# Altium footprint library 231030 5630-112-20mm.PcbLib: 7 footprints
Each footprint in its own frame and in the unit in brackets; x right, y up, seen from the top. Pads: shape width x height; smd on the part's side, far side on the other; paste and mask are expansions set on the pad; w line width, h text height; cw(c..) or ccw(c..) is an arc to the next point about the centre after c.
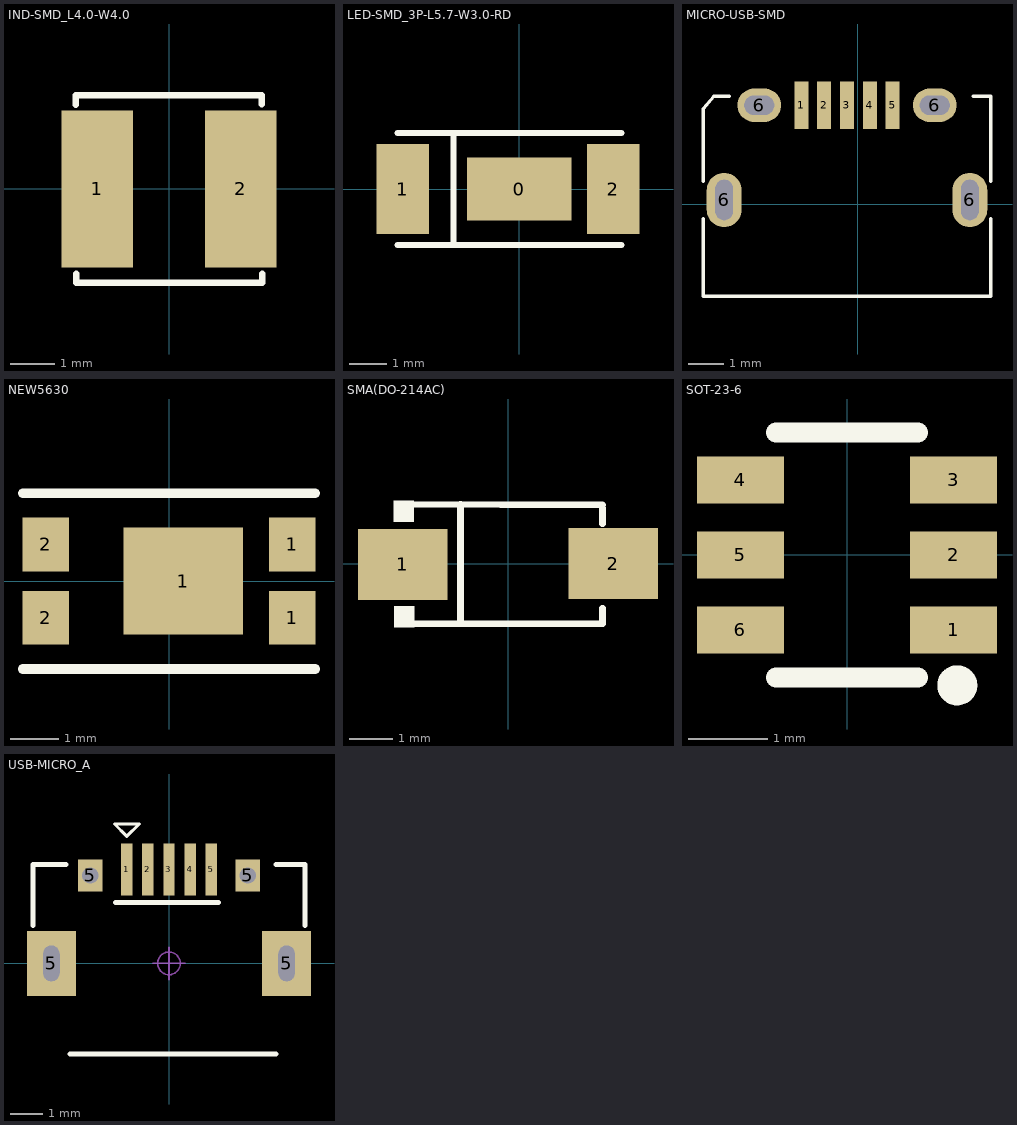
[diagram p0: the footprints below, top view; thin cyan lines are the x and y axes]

## IND-SMD_L4.0-W4.0 [mm]
pads (2):
  rect 1.6x3.5 smd: 1(-1.6,0) 2(1.6,0)
Top Overlay:
  lines w0.15: -2.08,1.88 -2.083,2.095 2.07,2.095 2.07,1.9 ; -2.07,-1.89 -2.07,-2.096 2.082,-2.096 2.08,-1.9

## LED-SMD_3P-L5.7-W3.0-RD [mm]
pads (3):
  rect 2.8x1.7 smd: 0(0,0)
  rect 1.4x2.4 smd: 1(-3.12,0) 2(2.52,0)
Top Overlay:
  lines w0.15: -3.261,-1.501 2.741,-1.501 ; -3.261,1.501 2.741,1.501 ; -1.76,-1.501 -1.76,1.501

## MICRO-USB-SMD [mm]
pads (9):
  rect 0.4x1.35 smd paste-100 mask+0.051: 1(-1.611,2.827) 2(-0.96,2.827) 3(-0.31,2.827) 4(0.34,2.827) 5(0.99,2.827)
  oval 1x1.55 hole 0.5 slot 1.15 at 90 deg: 6(-3.81,0.127) 6(3.19,0.127)
  oval 1.25x0.95 hole 0.55 slot 0.85 at 0 deg: 6(-2.81,2.827) 6(2.19,2.827)
Top Overlay:
  lines w0.1: -4.41,-0.405 -4.41,-2.073 -4.41,-2.624 -3.759,-2.624 3.5,-2.624 ; -4.41,0.659 -4.41,2.428 -4.41,2.728 -4.11,3.076 -3.66,3.076 ; 3.289,3.076 3.789,3.076 3.789,2.377 3.789,0.66 ; 3.391,-2.624 3.789,-2.624 3.789,-2.022 3.789,-0.406
Top Paste:
  drawing of 9 lines, arcs and shapes, not listed

## NEW5630 [mm]
height 6
pads (6):
  rrect50% 0.4x0.4 on Top Overlay: 0(-2.6,2.3)
  rect 2.45x2.2 smd mask+0: 1(0.295,0)
  rect 0.95x1.1 smd mask+0: 1(2.525,-0.75) 1(2.525,0.75) 2(-2.525,-0.75) 2(-2.525,0.75)
Top Overlay:
  lines w0.2: -3,-1.8 3,-1.8 ; -3,1.8 3,1.8
3D body "STW8Q2PA.STEP": height 0.9, standoff 0, extent -2.799,-1.499 2.801,1.501

## SMA(DO-214AC) [mm]
pads (2):
  rect 2.046x1.62 smd: 1(-2.404,-0.009) 2(2.404,0.009)
Top Overlay:
  region: -2.158,1.44 -2.158,0.962 -2.615,0.962 -2.615,1.44
  region: -2.145,-1.44 -2.145,-0.962 -2.602,-0.962 -2.602,-1.44
  lines w0.152: -2.526,1.364 2.159,1.346 ; -2.504,-1.364 2.165,-1.364 ; -1.085,-1.364 -1.085,1.364 ; 2.159,-1.364 2.159,-1.013 ; 2.159,0.919 2.159,1.27
Mechanical 6:
  region: -2.432,-0.097 -2.432,0.097 -1.659,0.097 -1.659,-0.097
  region: 2.432,-0.097 2.432,0.097 1.659,0.097 1.659,-0.097
  region: 2.142,-0.644 2.142,0.644 1.949,0.644 1.949,-0.644

## SOT-23-6 [mm]
pads (6):
  rect 1.1x0.6 smd paste+0 mask+0.051: 1(1.35,-0.95) 2(1.35,0) 3(1.35,0.95) 4(-1.35,0.95) 5(-1.35,0) 6(-1.35,-0.95)
Top Overlay:
  circle w0.254: c1.397,-1.651 r0.127
  lines w0.254: -0.9,-1.55 0.9,-1.55 ; -0.9,1.55 0.9,1.55
Mechanical 6:
  circle w0.2: c1.4,-0.95 r0.1

## USB-MICRO_A [mm] "micro型USB ，5.7*7.8*2.5mm"
height 0.5
pads (9):
  rect 0.35x1.6 smd: 1(-1.3,2.9) 2(-0.65,2.9) 3(0,2.9) 4(0.65,2.9) 5(1.3,2.9)
  rect 1.5x2 hole 0.5 slot 1.1 at 90 deg: 5(-3.625,0) 5(3.625,0)
  rect 0.762x1 hole 0.5: 5(-2.425,2.71) 5(2.425,2.71)
Top Overlay:
  lines w0.1: -1.681,4.297 -1.3,3.916 -0.919,4.297 -1.681,4.297
  lines w0.152: -4.191,1.168 -4.191,3.048 -3.175,3.048 ; -3.048,-2.794 3.302,-2.794 ; -1.65,1.875 1.525,1.875 ; 3.302,3.048 4.191,3.048 4.191,1.168
Mechanical 15:
  circle w0.05: c0,0 r0.35
  lines w0.05: -0.5,0 0.5,0 ; 0,-0.5 0,0.5
3D body "USB micro_A.STEP": height 2.8, standoff -0.95, extent -4.001,-2.71 4.001,2.89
